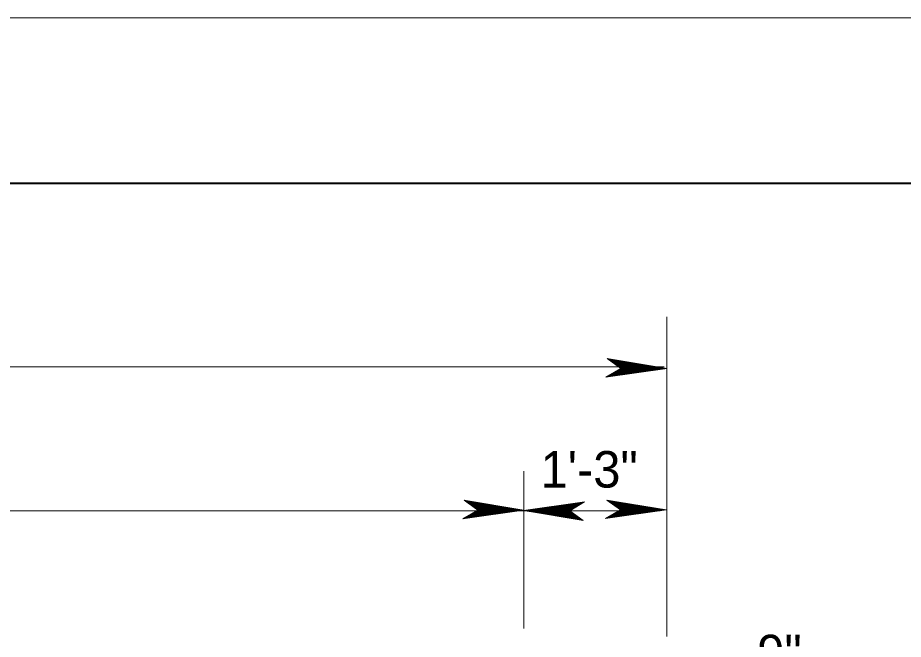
# Model space of a CAD drawing. Extents: x 144 to 252, y 360 to 425.
# Drawn here: x 174.95 to 182.91, y 419.9 to 425.48 of the extents above; entities that cross this region are included whole.
import ezdxf
from ezdxf.enums import TextEntityAlignment as Align

# ---------------------------------------------------------------- set-up
doc = ezdxf.new("R2010")
doc.units = 0
doc.header["$LTSCALE"] = 0.13
for name, color, linetype, lineweight in [('1', 7, 'Continuous', 40), ('16', 7, 'Continuous', 13), ('3', 7, 'Continuous', 13)]:
    doc.layers.add(name, color=color, linetype=linetype, lineweight=lineweight)

msp = doc.modelspace()

# ---------------------------------------------------------------- linework, layer by layer
at = {"layer": '1', "lineweight": 13}
for p, q in [((143.8112, 425.4823), (251.8112, 425.4823)), ((180.7812, 420.0186), (180.7812, 422.7941)), ((180.7812, 419.922), (180.7812, 420.0362))]:
    msp.add_line(p, q, dxfattribs=at)
at = {"layer": '1'}
msp.add_lwpolyline([(250.3172, 361.9183), (250.3172, 423.9913), (149.8112, 423.9913), (149.8112, 361.9183), (230.3642, 361.9183)], dxfattribs=at)
at = {"layer": '3'}
for p, q in [((180.7834, 422.3302), (180.2457, 422.4195)), ((180.2457, 422.4195), (180.3682, 422.3304)), ((180.769, 422.3309), (180.249, 422.4172)), ((180.7582, 422.3309), (180.2523, 422.4148)), ((180.7438, 422.3309), (180.2565, 422.4117)), ((180.731, 422.3309), (180.2602, 422.409)), ((180.7197, 422.3309), (180.2636, 422.4066)), ((180.7053, 422.3309), (180.2678, 422.4034)), ((180.6925, 422.3309), (180.2716, 422.4007)), ((180.6788, 422.3309), (180.2757, 422.3977)), ((156.7562, 422.3458), (180.7569, 422.3458)), ((180.3682, 422.3304), (180.2347, 422.2525)), ((180.2347, 422.2525), (180.7834, 422.3302)), ((180.2407, 422.256), (180.769, 422.3309)), ((180.2442, 422.258), (180.7582, 422.3309)), ((180.2488, 422.2607), (180.7438, 422.3309)), ((180.2528, 422.2631), (180.731, 422.3309)), ((180.2528, 422.2631), (180.731, 422.3309)), ((180.2565, 422.2652), (180.7197, 422.3309)), ((180.2611, 422.2679), (180.7053, 422.3309)), ((180.2652, 422.2703), (180.6925, 422.3309)), ((180.2696, 422.2728), (180.6788, 422.3309)), ((180.274, 422.2754), (180.6649, 422.3309)), ((180.2782, 422.2779), (180.6517, 422.3309)), ((180.6649, 422.3309), (180.2798, 422.3947)), ((180.2827, 422.2806), (180.6377, 422.3309)), ((180.6517, 422.3309), (180.2837, 422.3919)), ((180.2867, 422.2828), (180.6252, 422.3309)), ((180.6377, 422.3309), (180.2877, 422.3889)), ((180.2905, 422.2851), (180.6137, 422.3309)), ((180.6252, 422.3309), (180.2915, 422.3862)), ((180.6137, 422.3309), (180.2949, 422.3837)), ((180.2955, 422.2879), (180.5981, 422.3309)), ((180.5981, 422.3309), (180.2995, 422.3804)), ((180.2999, 422.2906), (180.5842, 422.3309)), ((180.5842, 422.3309), (180.3036, 422.3774)), ((180.3039, 422.2928), (180.5647, 422.3298)), ((180.3071, 422.2947), (180.5662, 422.3314)), ((180.5662, 422.3314), (180.3078, 422.3743)), ((180.3115, 422.2973), (180.5523, 422.3314)), ((180.5523, 422.3314), (180.312, 422.3713)), ((180.3157, 422.2998), (180.5392, 422.3314)), ((180.5392, 422.3314), (180.3158, 422.3685)), ((180.3173, 422.3007), (180.5301, 422.3309)), ((180.5301, 422.3309), (180.3196, 422.3657)), ((180.3212, 422.3029), (180.5181, 422.3309)), ((180.5181, 422.3309), (180.3232, 422.3632)), ((180.3256, 422.3056), (180.5042, 422.3309)), ((180.5042, 422.3309), (180.3272, 422.3602)), ((180.3306, 422.3084), (180.4886, 422.3309)), ((180.4886, 422.3309), (180.3319, 422.3569)), ((180.3347, 422.3108), (180.476, 422.3309)), ((180.476, 422.3309), (180.3356, 422.3542)), ((180.3389, 422.3133), (180.4627, 422.3309)), ((180.4627, 422.3309), (180.3395, 422.3513)), ((180.3427, 422.3156), (180.4507, 422.3309)), ((180.4507, 422.3309), (180.3431, 422.3487)), ((180.4363, 422.3309), (180.3473, 422.3457)), ((180.3474, 422.3182), (180.4363, 422.3309)), ((180.4224, 422.3309), (180.3515, 422.3427)), ((180.3518, 422.3208), (180.4224, 422.3309)), ((180.4098, 422.3309), (180.3552, 422.3399)), ((180.3559, 422.3232), (180.4098, 422.3309)), ((180.3965, 422.3309), (180.3591, 422.3371)), ((180.3612, 422.3262), (180.3862, 422.3298)), ((180.3851, 422.3309), (180.3625, 422.3347)), ((180.3638, 422.3278), (180.3851, 422.3309)), ((180.3749, 422.3309), (180.3655, 422.3324)), ((180.368, 422.3302), (180.7834, 422.3302)), ((179.497, 420.8483), (179.497, 421.4067)), ((180.7812, 420.8483), (180.7812, 421.4067)), ((179.4978, 421.0573), (178.9602, 421.1466)), ((178.9602, 421.1466), (179.0827, 421.0575)), ((179.4834, 421.058), (178.9634, 421.1442)), ((179.4726, 421.058), (178.9667, 421.1419)), ((179.4582, 421.058), (178.9709, 421.1387)), ((179.4454, 421.058), (178.9747, 421.1361)), ((179.4341, 421.058), (178.978, 421.1337)), ((179.4197, 421.058), (178.9822, 421.1305)), ((179.4069, 421.058), (178.986, 421.1277)), ((179.3932, 421.058), (178.9901, 421.1248)), ((180.0427, 421.1312), (179.4939, 421.0534)), ((180.0367, 421.1277), (179.5083, 421.0528)), ((180.0332, 421.1257), (179.5192, 421.0528)), ((180.0286, 421.123), (179.5336, 421.0528)), ((179.9091, 421.0532), (180.0427, 421.1312)), ((180.7802, 421.0598), (180.2426, 421.149)), ((180.2426, 421.149), (180.3651, 421.0599)), ((180.7658, 421.0604), (180.2458, 421.1467)), ((180.755, 421.0604), (180.2491, 421.1443)), ((180.7406, 421.0604), (180.2533, 421.1412)), ((180.7278, 421.0604), (180.2571, 421.1385)), ((180.7165, 421.0604), (180.2604, 421.1361)), ((180.7021, 421.0604), (180.2647, 421.1329)), ((180.6893, 421.0604), (180.2684, 421.1302)), ((180.6756, 421.0604), (180.2725, 421.1273)), ((180.6617, 421.0604), (180.2766, 421.1242)), ((156.7571, 421.0507), (179.4617, 421.0507)), ((179.0827, 421.0575), (178.9491, 420.9796)), ((178.9491, 420.9796), (179.4978, 421.0573)), ((178.9551, 420.9831), (179.4834, 421.058)), ((178.9586, 420.9851), (179.4726, 421.058)), ((178.9632, 420.9878), (179.4582, 421.058)), ((178.9673, 420.9902), (179.4454, 421.058)), ((178.9673, 420.9902), (179.4454, 421.058)), ((178.9709, 420.9923), (179.4341, 421.058)), ((178.9755, 420.995), (179.4197, 421.058)), ((178.9796, 420.9974), (179.4069, 421.058)), ((178.984, 420.9999), (179.3932, 421.058)), ((178.9884, 421.0025), (179.3793, 421.058)), ((178.9927, 421.005), (179.3661, 421.058)), ((179.3793, 421.058), (178.9942, 421.1218)), ((178.9972, 421.0077), (179.3522, 421.058)), ((179.3661, 421.058), (178.9981, 421.119)), ((179.0012, 421.0099), (179.3396, 421.058)), ((179.3522, 421.058), (179.0022, 421.116)), ((179.0049, 421.0122), (179.3282, 421.058)), ((179.3396, 421.058), (179.0059, 421.1133)), ((179.3282, 421.058), (179.0093, 421.1108)), ((179.0099, 421.015), (179.3125, 421.058)), ((179.3125, 421.058), (179.0139, 421.1075)), ((179.0143, 421.0177), (179.2987, 421.058)), ((179.2987, 421.058), (179.018, 421.1045)), ((179.0183, 421.0199), (179.2791, 421.0569)), ((179.0215, 421.0218), (179.2807, 421.0585)), ((179.2807, 421.0585), (179.0222, 421.1014)), ((179.0259, 421.0244), (179.2668, 421.0585)), ((179.2668, 421.0585), (179.0264, 421.0984)), ((179.2536, 421.0585), (179.0302, 421.0956)), ((179.0302, 421.0269), (179.2536, 421.0585)), ((179.0317, 421.0277), (179.2445, 421.058)), ((179.2445, 421.058), (179.034, 421.0928)), ((179.0356, 421.03), (179.2325, 421.058)), ((179.2325, 421.058), (179.0376, 421.0902)), ((179.04, 421.0327), (179.2187, 421.058)), ((179.2187, 421.058), (179.0417, 421.0872)), ((179.045, 421.0355), (179.203, 421.058)), ((179.203, 421.058), (179.0463, 421.084)), ((179.0491, 421.0379), (179.1904, 421.058)), ((179.1904, 421.058), (179.05, 421.0813)), ((179.0533, 421.0404), (179.1772, 421.058)), ((179.1772, 421.058), (179.0539, 421.0784)), ((179.0572, 421.0427), (179.1652, 421.058)), ((179.1652, 421.058), (179.0575, 421.0757)), ((179.1507, 421.058), (179.0617, 421.0727)), ((179.0618, 421.0453), (179.1507, 421.058)), ((179.1368, 421.058), (179.0659, 421.0697)), ((179.0662, 421.0479), (179.1368, 421.058)), ((179.1242, 421.058), (179.0696, 421.067)), ((179.0703, 421.0503), (179.1242, 421.058)), ((179.1109, 421.058), (179.0735, 421.0642)), ((179.0756, 421.0533), (179.1007, 421.0569)), ((179.0995, 421.058), (179.0769, 421.0617)), ((179.0782, 421.0549), (179.0995, 421.058)), ((179.0893, 421.058), (179.0799, 421.0595)), ((179.0824, 421.0573), (179.4978, 421.0573)), ((180.7231, 421.0507), (179.4617, 421.0507)), ((179.4939, 421.0534), (180.0316, 420.9642)), ((179.9093, 421.0534), (179.4939, 421.0534)), ((179.5083, 421.0528), (180.0283, 420.9665)), ((179.5192, 421.0528), (180.0251, 420.9688)), ((179.5336, 421.0528), (180.0208, 420.972)), ((180.0245, 421.1206), (179.5463, 421.0528)), ((180.0245, 421.1206), (179.5463, 421.0528)), ((179.5463, 421.0528), (180.0171, 420.9747)), ((180.0208, 421.1184), (179.5577, 421.0528)), ((179.5577, 421.0528), (180.0137, 420.9771)), ((180.0162, 421.1157), (179.5721, 421.0528)), ((179.5721, 421.0528), (180.0095, 420.9803)), ((180.0122, 421.1133), (179.5848, 421.0528)), ((179.5848, 421.0528), (180.0058, 420.983)), ((180.0077, 421.1108), (179.5986, 421.0528)), ((179.5986, 421.0528), (180.0017, 420.9859)), ((180.0033, 421.1082), (179.6124, 421.0528)), ((179.6124, 421.0528), (179.9976, 420.9889)), ((179.9991, 421.1058), (179.6257, 421.0528)), ((179.6257, 421.0528), (179.9937, 420.9917)), ((179.9946, 421.1031), (179.6396, 421.0528)), ((179.6396, 421.0528), (179.9896, 420.9948)), ((179.9906, 421.1008), (179.6522, 421.0528)), ((179.6522, 421.0528), (179.9858, 420.9974)), ((179.9868, 421.0986), (179.6636, 421.0528)), ((179.6636, 421.0528), (179.9824, 420.9999)), ((179.9818, 421.0958), (179.6792, 421.0528)), ((179.6792, 421.0528), (179.9778, 421.0032)), ((179.9774, 421.0931), (179.6931, 421.0528)), ((179.6931, 421.0528), (179.9737, 421.0062)), ((179.9702, 421.0889), (179.7111, 421.0522)), ((179.7111, 421.0522), (179.9695, 421.0093)), ((179.9734, 421.0908), (179.7127, 421.0538)), ((179.9658, 421.0863), (179.725, 421.0522)), ((179.725, 421.0522), (179.9653, 421.0123)), ((179.9616, 421.0838), (179.7382, 421.0522)), ((179.7382, 421.0522), (179.9615, 421.0152)), ((179.9601, 421.083), (179.7473, 421.0528)), ((179.7473, 421.0528), (179.9578, 421.0179)), ((179.9562, 421.0807), (179.7592, 421.0528)), ((179.7592, 421.0528), (179.9542, 421.0205)), ((179.9518, 421.0781), (179.7731, 421.0528)), ((179.7731, 421.0528), (179.9501, 421.0235)), ((179.9467, 421.0752), (179.7887, 421.0528)), ((179.7887, 421.0528), (179.9454, 421.0267)), ((179.9427, 421.0728), (179.8013, 421.0528)), ((179.8013, 421.0528), (179.9417, 421.0295)), ((179.9384, 421.0703), (179.8146, 421.0528)), ((179.8146, 421.0528), (179.9378, 421.0323)), ((179.9346, 421.0681), (179.8266, 421.0528)), ((179.8266, 421.0528), (179.9342, 421.035)), ((179.9299, 421.0654), (179.8411, 421.0528)), ((179.8411, 421.0528), (179.93, 421.038)), ((179.9255, 421.0628), (179.8549, 421.0528)), ((179.8549, 421.0528), (179.9258, 421.041)), ((179.9214, 421.0605), (179.8676, 421.0528)), ((179.8676, 421.0528), (179.9222, 421.0437)), ((179.8808, 421.0528), (179.9183, 421.0466)), ((179.9162, 421.0574), (179.8911, 421.0538)), ((179.9135, 421.0558), (179.8922, 421.0528)), ((179.8922, 421.0528), (179.9148, 421.049)), ((179.9024, 421.0528), (179.9118, 421.0512)), ((180.0316, 420.9642), (179.9091, 421.0532)), ((180.3651, 421.0599), (180.2315, 420.982)), ((180.2315, 420.982), (180.7802, 421.0598)), ((180.2375, 420.9855), (180.7658, 421.0604)), ((180.241, 420.9875), (180.755, 421.0604)), ((180.2456, 420.9902), (180.7406, 421.0604)), ((180.2497, 420.9926), (180.7278, 421.0604)), ((180.2497, 420.9926), (180.7278, 421.0604)), ((180.2533, 420.9948), (180.7165, 421.0604)), ((180.2579, 420.9974), (180.7021, 421.0604)), ((180.262, 420.9998), (180.6893, 421.0604)), ((180.2664, 421.0023), (180.6756, 421.0604)), ((180.2708, 421.0049), (180.6617, 421.0604)), ((180.2751, 421.0074), (180.6485, 421.0604)), ((180.2796, 421.0101), (180.6346, 421.0604)), ((180.6485, 421.0604), (180.2805, 421.1214)), ((180.2836, 421.0123), (180.622, 421.0604)), ((180.6346, 421.0604), (180.2846, 421.1184)), ((180.2873, 421.0146), (180.6106, 421.0604)), ((180.622, 421.0604), (180.2883, 421.1157)), ((180.6106, 421.0604), (180.2918, 421.1132)), ((180.2923, 421.0174), (180.5949, 421.0604)), ((180.5949, 421.0604), (180.2963, 421.1099)), ((180.2968, 421.0201), (180.5811, 421.0604)), ((180.5811, 421.0604), (180.3004, 421.1069)), ((180.3007, 421.0223), (180.5615, 421.0593)), ((180.3039, 421.0242), (180.5631, 421.0609)), ((180.5631, 421.0609), (180.3047, 421.1038)), ((180.3083, 421.0268), (180.5492, 421.0609)), ((180.5492, 421.0609), (180.3088, 421.1008)), ((180.3126, 421.0293), (180.536, 421.0609)), ((180.536, 421.0609), (180.3127, 421.098)), ((180.3141, 421.0302), (180.5269, 421.0604)), ((180.5269, 421.0604), (180.3164, 421.0952)), ((180.318, 421.0324), (180.5149, 421.0604)), ((180.5149, 421.0604), (180.32, 421.0927)), ((180.3224, 421.0351), (180.5011, 421.0604)), ((180.5011, 421.0604), (180.3241, 421.0897)), ((180.3274, 421.0379), (180.4854, 421.0604)), ((180.4854, 421.0604), (180.3287, 421.0864)), ((180.3315, 421.0403), (180.4728, 421.0604)), ((180.4728, 421.0604), (180.3324, 421.0837)), ((180.3357, 421.0428), (180.4596, 421.0604)), ((180.4596, 421.0604), (180.3363, 421.0808)), ((180.3396, 421.0451), (180.4476, 421.0604)), ((180.4476, 421.0604), (180.3399, 421.0782)), ((180.4331, 421.0604), (180.3442, 421.0752)), ((180.3442, 421.0478), (180.4331, 421.0604)), ((180.4193, 421.0604), (180.3483, 421.0722)), ((180.3487, 421.0503), (180.4193, 421.0604)), ((180.4066, 421.0604), (180.352, 421.0694)), ((180.3527, 421.0527), (180.4066, 421.0604)), ((180.3933, 421.0604), (180.3559, 421.0666)), ((180.358, 421.0557), (180.3831, 421.0593)), ((180.3819, 421.0604), (180.3593, 421.0642)), ((180.3607, 421.0573), (180.3819, 421.0604)), ((180.3717, 421.0604), (180.3623, 421.0619)), ((180.3648, 421.0598), (180.7802, 421.0598)), ((179.497, 420.8483), (179.497, 421.0023)), ((179.497, 420.7899), (179.497, 420.9528)), ((179.497, 419.9942), (179.497, 420.9528)), ((180.7812, 419.9342), (180.7812, 420.0362))]:
    msp.add_line(p, q, dxfattribs=at)

# ---------------------------------------------------------------- texts
at = {"layer": '16'}
msp.add_text('1\'-3"', height=0.3281, dxfattribs=at).set_placement((180.0841, 421.2607), align=Align.CENTER)
msp.add_text('9"', height=0.3281, dxfattribs=at).set_placement((181.5942, 419.6103))

doc.saveas('drawing.dxf')
